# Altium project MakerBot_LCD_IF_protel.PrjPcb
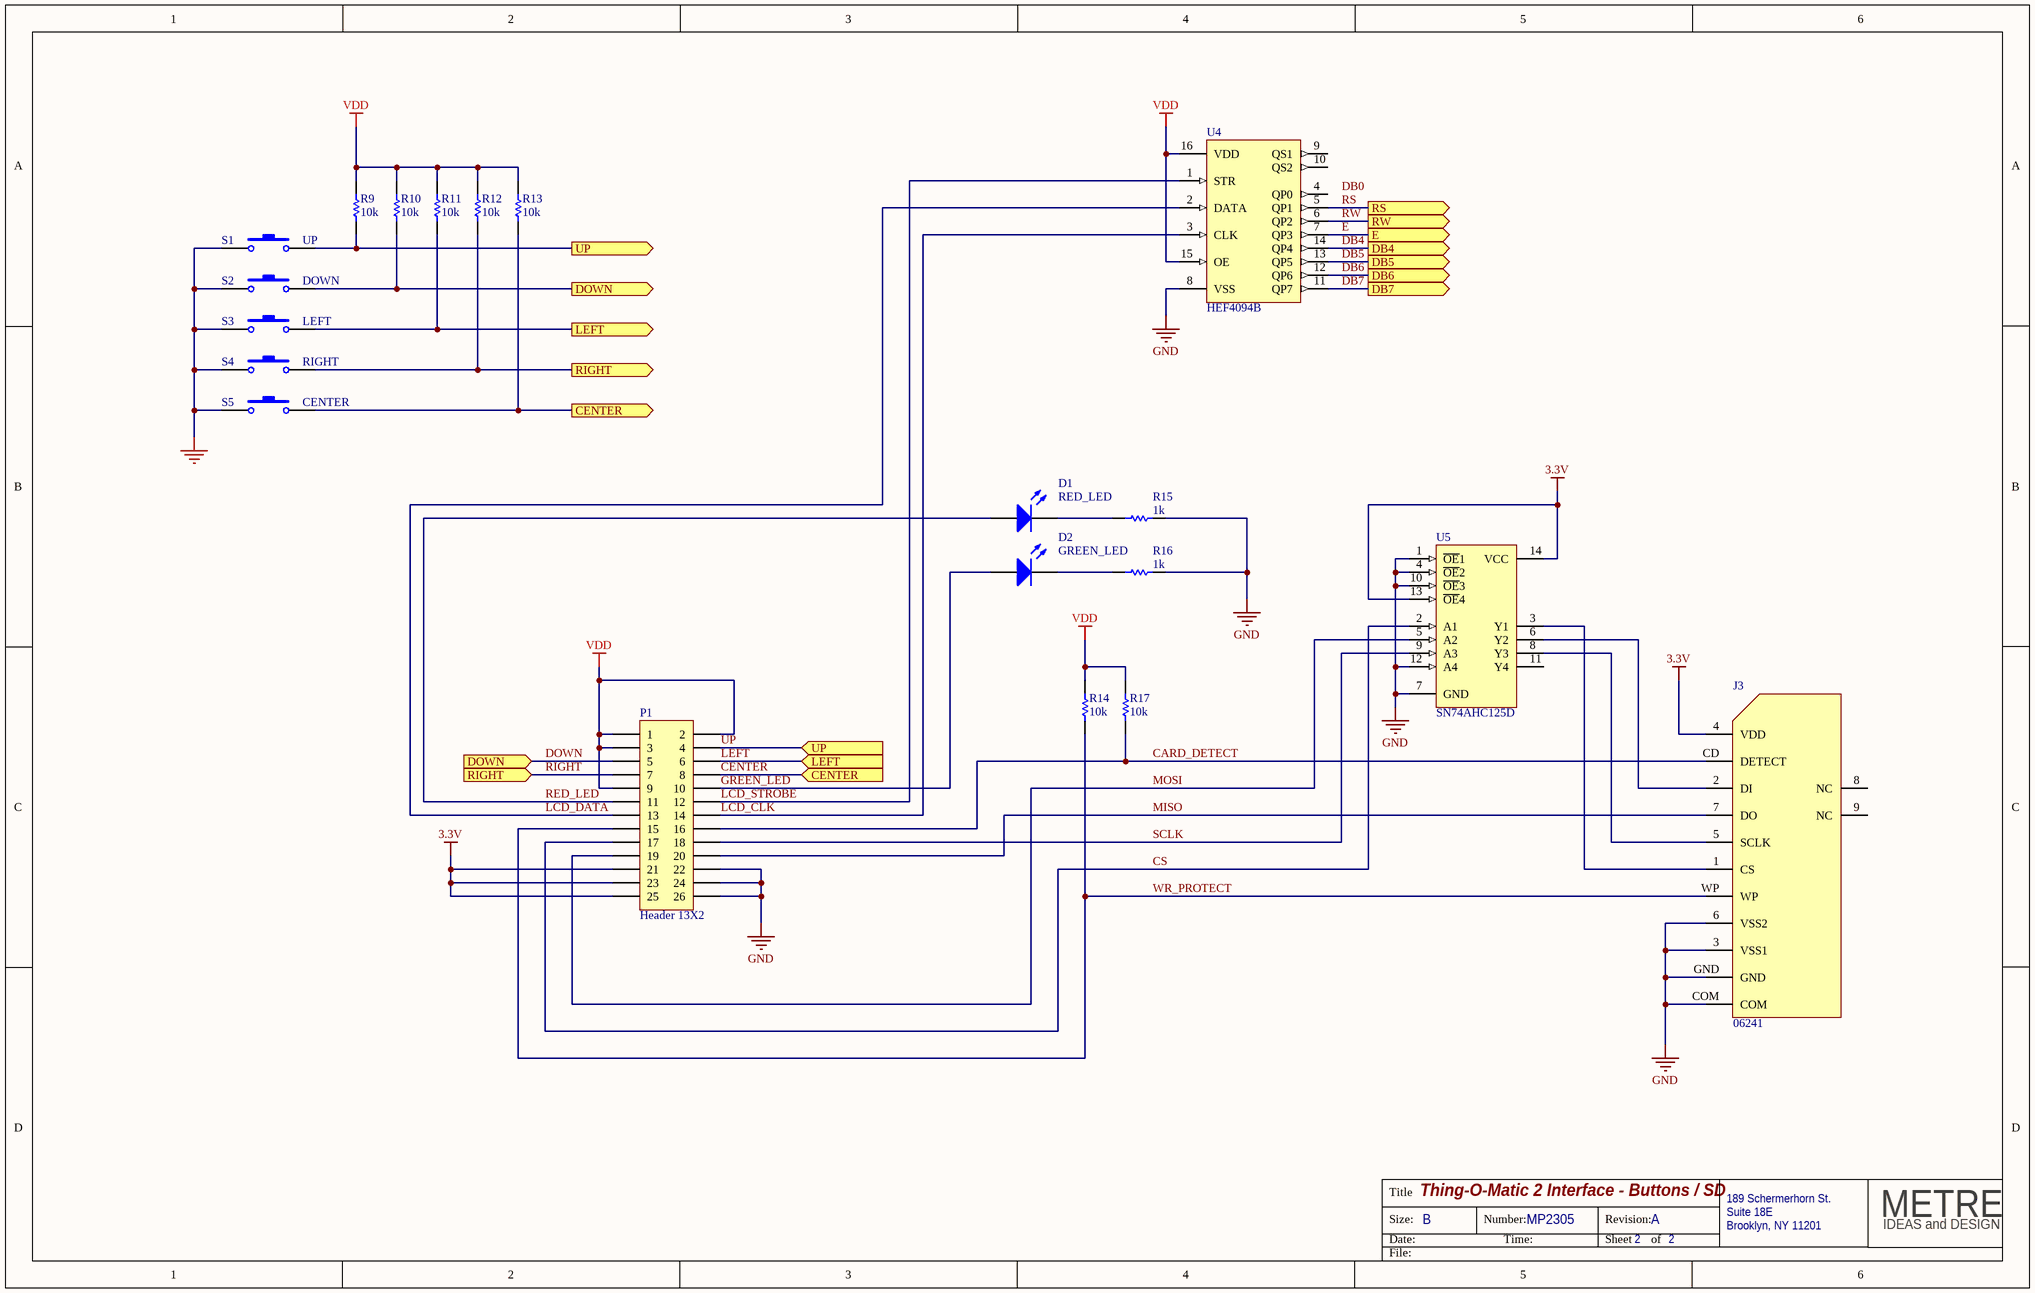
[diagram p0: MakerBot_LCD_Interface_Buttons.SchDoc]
1 sheet, 20 parts. Net scope: flat (ports and power ports of the same name join across sheets).

## Sheet MakerBot_LCD_Interface_Buttons.SchDoc: Thing-O-Matic 2 Interface - Buttons / SD
size B; CompanyName: Metre Ideas and Design; DrawnBy: W. Sakran; Address1: 189 Schermerhorn St.; Address2: Suite 18E; Address3: Brooklyn, NY 11201; DocumentNumber: MP2305; Revision: A; SheetNumber: 2; SheetTotal: 2; PageSetup: Record=PageOptions|CenterHorizontal=True|CenterVertical=True|PrintScale=0.71|XCorrection=1.00|YCorrection=1.00|PrintKind=1|BorderSize=5000000|LeftOffset=0|BottomOffset=0|Orientation=2|PaperLength=1000|PaperWidth=1000|Scale=100|PaperSource=259|PrintQuality=600|MediaType=1|DitherType=10|PaperKind=Letter 8.5x11in.|PrintScaleMode=1

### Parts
D1  RED_LED  [1206 LED, REVERSE]
D2  GREEN_LED  [1206 LED, REVERSE]
J3  06241  [06241]
P1  Header 13X2  [26-PIN SMT HEADER]
R9  value 10k  [RESC2012N]  (hidden comment: Res1)
R10  value 10k  [RESC2012N]  (hidden comment: Res1)
R11  value 10k  [RESC2012N]  (hidden comment: Res1)
R12  value 10k  [RESC2012N]  (hidden comment: Res1)
R13  value 10k  [RESC2012N]  (hidden comment: Res1)
R14  value 10k  [RESC2012N]  (hidden comment: Res1)
R15  value 1k  [RESC2012N]  (hidden comment: Res1)
R16  value 1k  [RESC2012N]  (hidden comment: Res1)
R17  value 10k  [RESC2012N]  (hidden comment: Res1)
S1  UP  [6mm Shorting Pad]
S2  DOWN  [6mm Shorting Pad]
S3  LEFT  [6mm Shorting Pad]
S4  RIGHT  [6mm Shorting Pad]
S5  CENTER  [6mm Shorting Pad]
U4  HEF4094B  [SOIC127P602-16AN]
U5  SN74AHC125D  [D014_N]

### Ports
CENTER (in), CENTER (out), DB4 (out), DB5 (out), DB6 (out), DB7 (out), DOWN (in), DOWN (out), E (out), LEFT (in), LEFT (out), RIGHT (in), RIGHT (out), RS (out), RW (out), UP (in), UP (out)

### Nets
3.3V: J3.4(VDD) P1.21 P1.23 P1.25 U5.13(~{OE}4) U5.14(VCC)
GND: J3.3(VSS1) J3.6(VSS2) J3.COM J3.GND P1.22 P1.24 P1.26 R15.1 R16.1 U4.8(VSS) U5.1(~{OE}1) U5.4(~{OE}2) U5.7(GND) U5.10(~{OE}3) U5.12(A4)
VDD: P1.1 P1.2 P1.3 P1.9 R9.2 R10.2 R11.2 R12.2 R13.2 R14.2 R17.2 U4.15(OE) U4.16(VDD)
VSS: S1.1 S2.1 S3.1 S4.1 S5.1
CARD_DETECT: J3.CD(DETECT) P1.16 R17.1
CENTER: P1.8 R13.1 S5.2 ; port CENTER
CS: P1.17 U5.2(A1)
DB4: U4.14(QP4) ; port DB4
DB5: U4.13(QP5) ; port DB5
DB6: U4.12(QP6) ; port DB6
DB7: U4.11(QP7) ; port DB7
DOWN: P1.5 R10.1 S2.2 ; port DOWN
E: U4.7(QP3) ; port E
GREEN_LED: D2.1(A) P1.10
LCD_CLK: P1.14 U4.3(CLK)
LCD_DATA: P1.13 U4.2(DATA)
LCD_STROBE: P1.12 U4.1(STR)
LEFT: P1.6 R11.1 S3.2 ; port LEFT
MISO: J3.7(DO) P1.20
MOSI: P1.19 U5.5(A2)
RED_LED: D1.1(A) P1.11
RIGHT: P1.7 R12.1 S4.2 ; port RIGHT
RS: U4.5(QP1) ; port RS
RW: U4.6(QP2) ; port RW
SCLK: P1.18 U5.9(A3)
UP: P1.4 R9.1 S1.2 ; port UP
WR_PROTECT: J3.WP P1.15 R14.1
NetD1_2: D1.2(K) R15.2
NetD2_2: D2.2(K) R16.2
NetJ3_1: J3.1(CS) U5.3(Y1)
NetJ3_2: J3.2(DI) U5.6(Y2)
NetJ3_5: J3.5(SCLK) U5.8(Y3)

Not connected (* = marked no-connect by the designer): J3 8(NC) 9(NC); U4 4(QP0) 9(QS1) 10(QS2); U5 11(Y4)

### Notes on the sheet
- Labels drawn without touching a wire or pin: DB0

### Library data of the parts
D1 D2 = LED2: Typical RED, GREEN, YELLOW, AMBER GaAs LED
J3 = 06241: SD Card Slot, Push In / Push Out, Reverse
P1 = Header 13X2: Header, 13-Pin, Dual row
R9-R17 = Res1: Resistor
S1-S5 = SW-PB: Switch
U4 = HEF4094B: 8-Stage Shift and Store Register
U5 = SN74AHC125D: Quadruple Bus Buffer Gate with 3-State Outputs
